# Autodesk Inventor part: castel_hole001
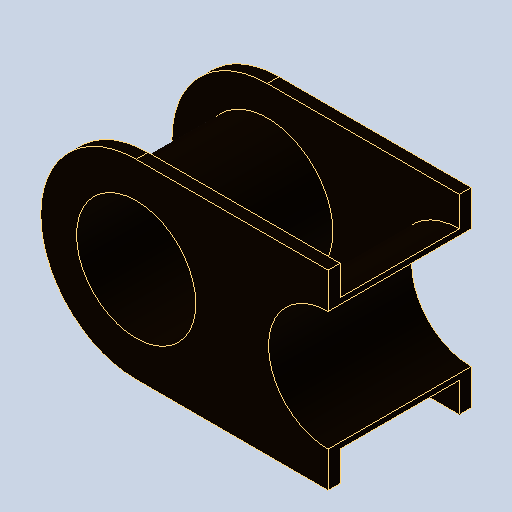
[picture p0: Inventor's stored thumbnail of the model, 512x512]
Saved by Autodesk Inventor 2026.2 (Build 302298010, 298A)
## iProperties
Created: 2026-10
Part Number: castel_hole001
Material: Générique
Document SubType Name: Modeling
Designer: mel
Density: 1 g/cm^3
Appearance: Par défaut
Author: mel
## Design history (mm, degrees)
feature "Base1"
node "Solide1"
